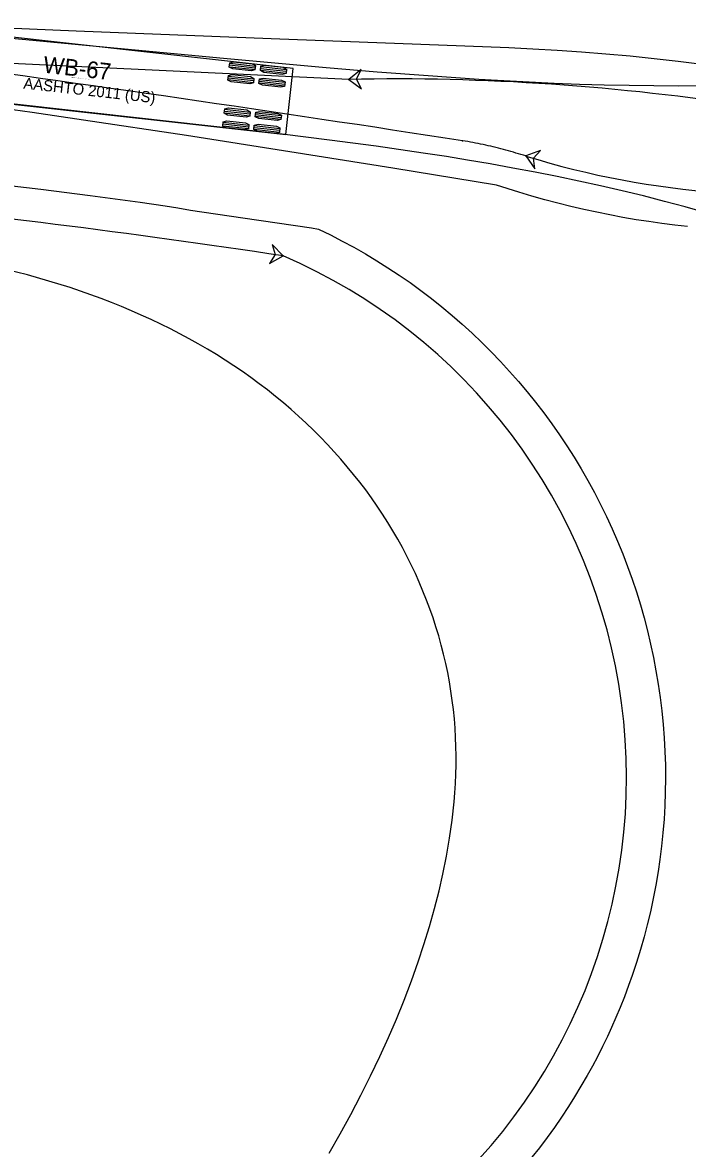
# Model space of a CAD drawing. Extents: x 2175591 to 2194071, y 76570 to 86955.
# Drawn here: x 2176363 to 2176448.1, y 77272.9 to 77416.8 of the extents above; entities that cross this region are included whole.
import ezdxf

# ---------------------------------------------------------------- set-up
doc = ezdxf.new("R2010")
doc.units = 0
doc.layers.add('C-UTIL-STRM-TEXT', color=7, linetype='Continuous')

msp = doc.modelspace()

# ---------------------------------------------------------------- linework, layer by layer
at = {"layer": 'C-UTIL-STRM-TEXT'}
for p, q in [((2176397.66, 77410.98), (2176344.98, 77416.85)), ((2176404.76, 77409.58), (2176328.01, 77413.21)), ((2176389.48, 77411.2), (2176392.76, 77410.83)), ((2176389.5, 77411.43), (2176392.78, 77411.06)), ((2176389.53, 77411.65), (2176392.81, 77411.29)), ((2176393.45, 77410.76), (2176396.73, 77410.39)), ((2176393.48, 77410.98), (2176396.76, 77410.62)), ((2176393.51, 77411.21), (2176396.79, 77410.85)), ((2176396.71, 77402.53), (2176397.66, 77410.98)), ((2176389.3, 77409.56), (2176392.58, 77409.19)), ((2176389.32, 77409.79), (2176392.6, 77409.42)), ((2176389.35, 77410.01), (2176392.63, 77409.65)), ((2176393.3, 77409.34), (2176396.58, 77408.98)), ((2176393.32, 77409.57), (2176396.6, 77409.21)), ((2176344.04, 77408.4), (2176396.71, 77402.53)), ((2176393.27, 77409.12), (2176396.55, 77408.75)), ((2176388.82, 77405.3), (2176392.1, 77404.94)), ((2176388.85, 77405.53), (2176392.13, 77405.16)), ((2176388.87, 77405.76), (2176392.15, 77405.39)), ((2176392.82, 77405.09), (2176396.1, 77404.72)), ((2176392.85, 77405.31), (2176396.13, 77404.95)), ((2176388.64, 77403.66), (2176391.92, 77403.3)), ((2176388.67, 77403.89), (2176391.94, 77403.52)), ((2176388.69, 77404.12), (2176391.97, 77403.75)), ((2176392.67, 77403.67), (2176395.95, 77403.31)), ((2176392.8, 77404.86), (2176396.08, 77404.49)), ((2176392.62, 77403.22), (2176395.89, 77402.85)), ((2176392.64, 77403.45), (2176395.92, 77403.08))]:
    msp.add_line(p, q, dxfattribs=at)
for points in [[(2176344.98, 77416.85), (2176369.89, 77415.79), (2176394.81, 77414.79), (2176425.24, 77413.65), (2176428.29, 77413.5), (2176431.41, 77413.32), (2176434.52, 77413.1), (2176437.63, 77412.85), (2176440.73, 77412.57), (2176443.82, 77412.26), (2176446.9, 77411.92), (2176449.98, 77411.54)], [(2176349.38, 77415.98), (2176388.74, 77412.31), (2176401.85, 77411.12), (2176408.38, 77410.56), (2176414.89, 77410.06), (2176421.38, 77409.62), (2176424.61, 77409.43), (2176427.83, 77409.26), (2176431.04, 77409.11), (2176434.25, 77408.99), (2176437.43, 77408.89), (2176440.61, 77408.82), (2176443.77, 77408.78), (2176446.92, 77408.77), (2176450.06, 77408.79)], [(2176450.44, 77392.52), (2176447.8, 77393.27), (2176445.13, 77393.99), (2176442.44, 77394.68), (2176439.72, 77395.34), (2176436.97, 77395.97), (2176434.2, 77396.58), (2176431.41, 77397.16), (2176428.59, 77397.72), (2176425.76, 77398.25), (2176422.86, 77398.77), (2176419.93, 77399.27), (2176417.25, 77399.71), (2176414.26, 77400.17), (2176408.25, 77401.04), (2176402.3, 77401.83), (2176396.25, 77402.57), (2176344.07, 77408.4)], [(2176448.1, 77390.77), (2176446.47, 77390.95), (2176444.82, 77391.16), (2176443.15, 77391.4), (2176441.5, 77391.65), (2176439.83, 77391.94), (2176438.16, 77392.25), (2176436.49, 77392.59), (2176434.82, 77392.95), (2176433.16, 77393.34), (2176431.49, 77393.75), (2176429.83, 77394.19), (2176428.18, 77394.65), (2176426.52, 77395.15), (2176423.64, 77396.06), (2176410.4, 77398.23), (2176397.2, 77400.34), (2176384.01, 77402.39), (2176370.82, 77404.37), (2176364.27, 77405.33), (2176358.01, 77406.21)], [(2176427.42, 77399.79), (2176427.1, 77399.89), (2176426.78, 77399.98), (2176426.46, 77400.08), (2176426.14, 77400.17), (2176425.82, 77400.27), (2176425.5, 77400.36), (2176425.18, 77400.45), (2176424.86, 77400.54), (2176424.54, 77400.62), (2176424.21, 77400.71), (2176423.89, 77400.79), (2176423.57, 77400.87), (2176423.24, 77400.95), (2176422.92, 77401.03), (2176422.59, 77401.1), (2176422.27, 77401.17), (2176421.94, 77401.24), (2176421.62, 77401.31), (2176421.29, 77401.38), (2176420.96, 77401.44), (2176420.63, 77401.5), (2176420.31, 77401.56), (2176419.98, 77401.62), (2176419.65, 77401.68), (2176419.32, 77401.73)], [(2176359.09, 77396.29), (2176365.35, 77395.53), (2176371.66, 77394.73), (2176378.05, 77393.88), (2176381.29, 77393.43), (2176382.91, 77393.17), (2176384.52, 77392.86), (2176391.22, 77391.9), (2176400, 77390.59), (2176400.9, 77390.44), (2176402.42, 77389.7), (2176403.92, 77388.92), (2176405.41, 77388.12), (2176406.88, 77387.28), (2176408.34, 77386.41), (2176409.77, 77385.5), (2176411.19, 77384.57), (2176412.59, 77383.6), (2176413.97, 77382.6), (2176415.32, 77381.57), (2176416.66, 77380.51), (2176417.97, 77379.41), (2176419.26, 77378.29), (2176420.52, 77377.14), (2176421.76, 77375.96), (2176422.98, 77374.76), (2176424.17, 77373.52), (2176425.33, 77372.26), (2176426.47, 77370.97), (2176427.57, 77369.66), (2176428.65, 77368.32), (2176429.7, 77366.96), (2176430.72, 77365.57), (2176431.71, 77364.16), (2176432.66, 77362.73), (2176433.59, 77361.28), (2176434.48, 77359.8), (2176435.34, 77358.31), (2176436.17, 77356.79), (2176436.97, 77355.26), (2176437.73, 77353.71), (2176438.45, 77352.14), (2176439.14, 77350.56), (2176439.8, 77348.96), (2176440.42, 77347.34), (2176441, 77345.72), (2176441.55, 77344.08), (2176442.06, 77342.42), (2176442.53, 77340.76), (2176442.97, 77339.08), (2176443.37, 77337.4), (2176443.73, 77335.7), (2176444.05, 77334), (2176444.34, 77332.29), (2176444.59, 77330.58), (2176444.8, 77328.86), (2176444.97, 77327.14), (2176445.1, 77325.41), (2176445.19, 77323.68), (2176445.25, 77321.95), (2176445.26, 77320.22), (2176445.24, 77318.48), (2176445.18, 77316.75), (2176445.08, 77315.02), (2176444.94, 77313.3), (2176444.76, 77311.58), (2176444.55, 77309.86), (2176444.32, 77308.32), (2176444.03, 77306.6), (2176443.71, 77304.9), (2176443.34, 77303.2), (2176442.94, 77301.52), (2176442.54, 77300), (2176442.08, 77298.36), (2176441.57, 77296.71), (2176441.02, 77295.07), (2176440.55, 77293.75), (2176440.02, 77292.33), (2176439.47, 77290.95), (2176438.92, 77289.66), (2176438.36, 77288.39), (2176437.84, 77287.26), (2176437.22, 77285.98), (2176436.56, 77284.67), (2176435.91, 77283.45), (2176435.25, 77282.26), (2176434.46, 77280.89), (2176433.64, 77279.54), (2176432.86, 77278.3), (2176431.97, 77276.96), (2176431.06, 77275.64), (2176430.12, 77274.33), (2176429.14, 77273.04), (2176428.18, 77271.82)], [(2176402.26, 77272.36), (2176403.66, 77274.82), (2176405.01, 77277.28), (2176406.31, 77279.75), (2176407.55, 77282.22), (2176408.73, 77284.69), (2176409.84, 77287.14), (2176410.84, 77289.47), (2176411.83, 77291.89), (2176412.78, 77294.36), (2176413.65, 77296.81), (2176414.37, 77298.99), (2176415.08, 77301.3), (2176415.74, 77303.63), (2176416.31, 77305.88), (2176416.79, 77308.01), (2176417.25, 77310.29), (2176417.65, 77312.61), (2176417.97, 77314.92), (2176418.22, 77317.25), (2176418.32, 77318.41), (2176418.39, 77319.58), (2176418.44, 77320.76), (2176418.48, 77321.94), (2176418.48, 77323.11), (2176418.47, 77324.3), (2176418.42, 77325.48), (2176418.36, 77326.66), (2176418.26, 77327.85), (2176418.14, 77329.03), (2176418, 77330.21), (2176417.83, 77331.4), (2176417.63, 77332.58), (2176417.41, 77333.76), (2176417.16, 77334.93), (2176416.88, 77336.1), (2176416.58, 77337.27), (2176416.26, 77338.44), (2176415.9, 77339.6), (2176415.53, 77340.75), (2176415.12, 77341.9), (2176414.7, 77343.04), (2176414.24, 77344.17), (2176413.77, 77345.3), (2176413.27, 77346.42), (2176412.74, 77347.53), (2176412.19, 77348.64), (2176411.61, 77349.73), (2176411.01, 77350.82), (2176410.39, 77351.89), (2176409.74, 77352.95), (2176409.07, 77354.01), (2176408.38, 77355.05), (2176407.66, 77356.08), (2176406.92, 77357.1), (2176406.16, 77358.1), (2176405.38, 77359.1), (2176404.57, 77360.08), (2176403.75, 77361.04), (2176402.9, 77361.99), (2176402.03, 77362.93), (2176401.14, 77363.85), (2176400.23, 77364.76), (2176399.3, 77365.66), (2176398.34, 77366.53), (2176397.37, 77367.4), (2176396.39, 77368.24), (2176395.38, 77369.07), (2176394.35, 77369.89), (2176393.31, 77370.68), (2176392.24, 77371.46), (2176391.16, 77372.23), (2176390.06, 77372.97), (2176388.95, 77373.7), (2176387.82, 77374.41), (2176386.67, 77375.11), (2176385.51, 77375.78), (2176384.33, 77376.44), (2176383.14, 77377.08), (2176381.93, 77377.7), (2176380.71, 77378.31), (2176379.47, 77378.9), (2176378.22, 77379.46), (2176376.96, 77380.02), (2176375.68, 77380.55), (2176374.39, 77381.07), (2176373.09, 77381.57), (2176371.77, 77382.05), (2176369.11, 77382.96), (2176366.4, 77383.8), (2176363.65, 77384.58), (2176360.86, 77385.29)]]:
    msp.add_lwpolyline(points, dxfattribs=at)
for points in [[(2176389.47, 77411.14), (2176389.54, 77411.71), (2176390.01, 77411.83), (2176392.38, 77411.57), (2176392.82, 77411.35), (2176392.75, 77410.78), (2176392.27, 77410.66), (2176389.91, 77410.92)], [(2176393.45, 77410.7), (2176393.51, 77411.27), (2176393.99, 77411.39), (2176396.35, 77411.13), (2176396.79, 77410.9), (2176396.73, 77410.33), (2176396.25, 77410.21), (2176393.89, 77410.48)], [(2176404.76, 77409.58), (2176406.37, 77408.39), (2176405.76, 77409.6), (2176406.32, 77410.83)], [(2176389.29, 77409.5), (2176389.35, 77410.07), (2176389.83, 77410.19), (2176392.19, 77409.93), (2176392.63, 77409.71), (2176392.57, 77409.14), (2176392.09, 77409.02), (2176389.73, 77409.28)], [(2176393.27, 77409.06), (2176393.33, 77409.63), (2176393.81, 77409.75), (2176396.17, 77409.49), (2176396.61, 77409.26), (2176396.55, 77408.69), (2176396.07, 77408.57), (2176393.71, 77408.84)], [(2176388.82, 77405.25), (2176388.88, 77405.81), (2176389.36, 77405.93), (2176391.72, 77405.67), (2176392.16, 77405.45), (2176392.1, 77404.88), (2176391.62, 77404.76), (2176389.26, 77405.02)], [(2176392.79, 77404.8), (2176392.85, 77405.37), (2176393.33, 77405.49), (2176395.69, 77405.23), (2176396.13, 77405.01), (2176396.07, 77404.44), (2176395.59, 77404.32), (2176393.23, 77404.58)], [(2176388.63, 77403.61), (2176388.7, 77404.17), (2176389.17, 77404.29), (2176391.54, 77404.03), (2176391.98, 77403.81), (2176391.91, 77403.24), (2176391.43, 77403.12), (2176389.07, 77403.38)], [(2176392.61, 77403.16), (2176392.67, 77403.73), (2176393.15, 77403.85), (2176395.51, 77403.59), (2176395.95, 77403.37), (2176395.89, 77402.8), (2176395.41, 77402.68), (2176393.05, 77402.94)], [(2176427.42, 77399.79), (2176428.57, 77398.15), (2176428.37, 77399.49), (2176429.29, 77400.48)], [(2176396.35, 77387.03), (2176394.96, 77388.47), (2176395.36, 77387.18), (2176394.6, 77386.06)]]:
    msp.add_lwpolyline(points, close=True, dxfattribs=at)
for centre in [(2176404.76, 77409.58), (2176404.76, 77409.58), (2176419.32, 77401.73), (2176419.32, 77401.73), (2176427.42, 77399.79), (2176427.42, 77399.79), (2176396.35, 77387.03), (2176396.35, 77387.03)]:
    msp.add_circle(centre, 0.0417, dxfattribs=at)
for centre, radius, start, end in [((2176459.84, 77504.15), 109.29, 252.7407, 305.2998), ((2175794.38, 73359.16), 4090.59, 81.21218, 82.23197), ((2176410.61, 77113.72), 295.92, 81.0842, 91.1323), ((2176211.19, 76154.06), 1246.79, 81.45937, 84.16527), ((2176367.74, 77320.37), 72.54, 308.3375, 66.7693)]:
    msp.add_arc(centre, radius, start, end, dxfattribs=at)

# ---------------------------------------------------------------- texts
for s, height, p in [('WB-67', 2.125, (2176365.59, 77410.45)), ('AASHTO 2011 (US)', 1.4167, (2176363.09, 77408.41)), ('(c) 2019 Transoft Solutions, Inc. All rights reserved.', 0.085, (2176369.12, 77409.84))]:
    msp.add_text(s, height=height, rotation=353.6431, dxfattribs=at).set_placement(p)

doc.saveas('drawing.dxf')
